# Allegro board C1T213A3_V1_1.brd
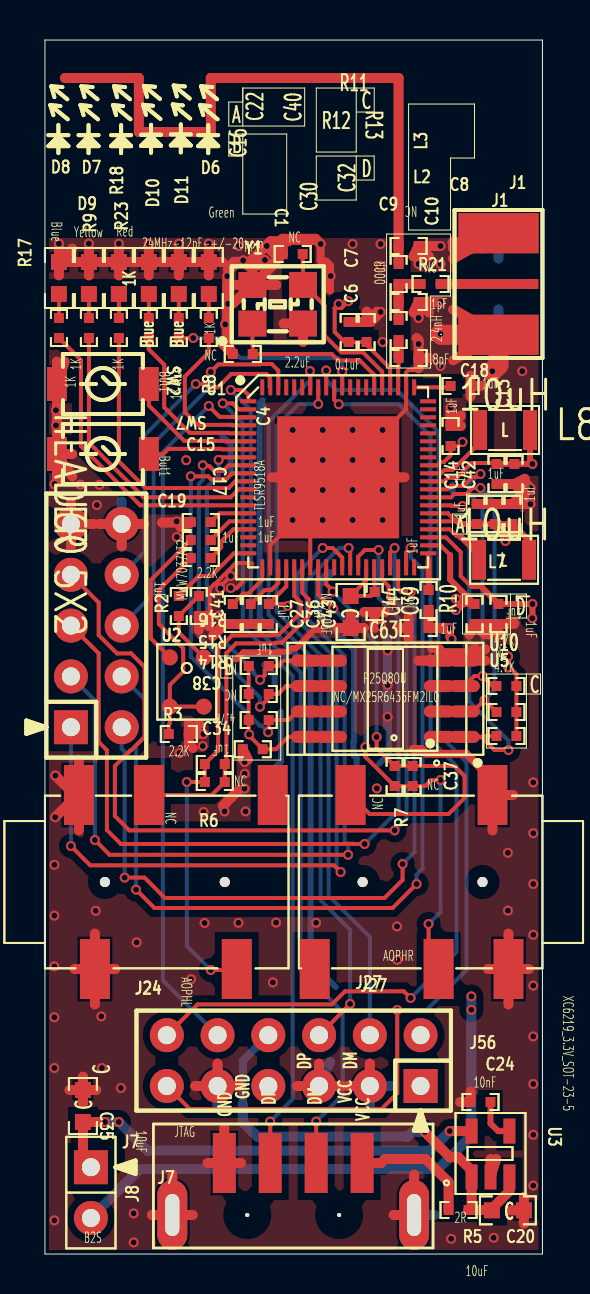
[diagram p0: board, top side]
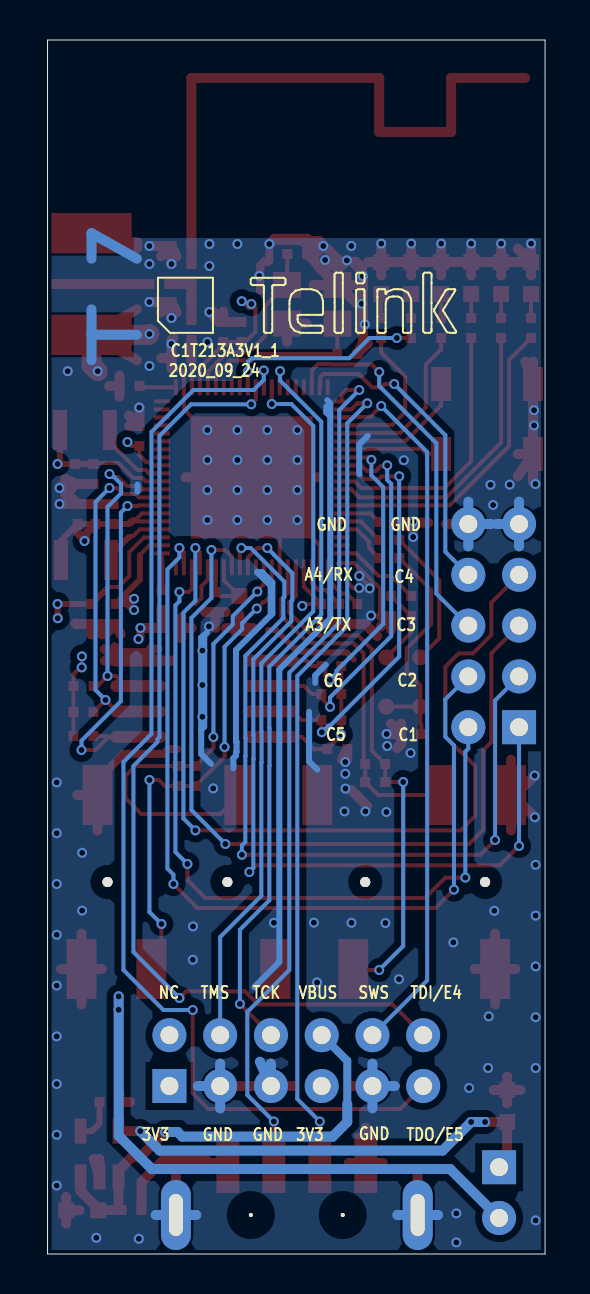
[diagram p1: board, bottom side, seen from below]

Outline 24.9 x 60.7 mm; copper layers: TOP, GND, POWER, BOTTOM. Coordinates in mm from the lower left corner of the outline.
Outline path: 0,60.7 0,0 24.9,0 24.9,60.7 0,60.7

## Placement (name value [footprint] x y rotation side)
C1  NC  [0402]  12.4 50 0 top
C4  NC  [0402]  9.9 45 0 top
C6  2.2uF  [0402]  15.2 46.1 90 top
C7  0.1uF  [0402]  16.1 46.1 90 top
C8  1.8pF  [0402]  18.2 44.8 180 top
C9  1pF  [0402]  18.2 47.6 180 top
C10  1pF  [0402]  18.2 50.4 180 top
C13  1uF  [0402]  20.3 40.9 90 top
C14  1uF  [0402]  22.6 39 270 top
C15  1uF  [0402]  7.8 36.6 0 top
C16  1uF  [0402]  22.5 37 90 top
C17  1uF  [0402]  7.8 35.7 0 top
C18  1uF  [0402]  20.8 43.4 0 top
C19  1uF  [0402]  7.8 34.8 0 top
C20  10uF  [0603C]  23.17 2.18 0 top
C22  1uF  [0402]  21.6 37 90 top
C24  10nF  [0402]  21.8 7.6 180 top
C27  1uF  [0402]  9.4 32 270 top
C30  1uF  [0402]  21.5 32 270 top
C32  1uF  [0402]  22.7 32 270 top
C34  NC  [0402]  8.5 24.5 0 top
C35  10uF  [0603C]  1.9 7.4 90 top
C36  1uF  [0402]  10.3 32 270 top
C37  NC  [0402]  18.4 23.9 90 top
C38  1uF  [0402]  10.4 25.24 180 top
C39  1uF  [0402]  16.5 32.6 270 top
C40  1uF  [0402]  23.4 37 90 top
C41  1uF  [0402]  7.7 32.4 270 top
C42  1uF  [0402]  23.5 39 270 top
C43  1uF  [0402]  11.2 32 270 top
C44  NC/10uF  [0603C]  15.3 32.1 270 top
C63  1uF  [0402]  18.7 31.3 180 top
D6  Green  [0603-LED]  8.2 48.8 90 top
D7  Yellow  [0603-LED]  2.2 48.8 90 top
D8  Blue  [0603-LED]  0.7 48.8 90 top
D9  Red  [0603-LED]  3.7 48.8 90 top
D10  White  [0603-LED]  5.2 48.8 90 top
D11  Orange  [0603-LED]  6.7 48.8 90 top
J1  RFIN  [SMA-H]  22.7 48.5 180 top
J7  USB_SMT_4PIN  [USB-M-4]  12.43 4.55 90 top
J8  B2S  [HDR254F-1X2X850]  2.3 1.8 90 top
J24  AOPHL  [PJ-327]  0 18.6 90 top
J27  AOPHR  [PJ-327]  24.9 18.6 270 top
J56  JTAG  [HDR254F-2X6X850]  6.1 8.4 0 top
J60  HEADER 5X2  [HDR254F-2X5X850]  1.3 36.5 270 top
L2  2.4nH  [0402]  17.7 46.2 90 top
L3  3.3nH  [0402]  17.7 49 90 top
L7  10uH  [1008L]  22.98 34.71 0 top
L8  10uH  [1008L]  23.03 41.2 0 top
R2  2.2K  [0402]  6.7 32.4 270 top
R3  2.2K  [0402]  6.7 26 180 top
R5  2R  [0402]  20.7 2.2 0 top
R6  NC  [0402]  8.5 23.6 0 top
R7  NC  [0402]  17.5 23.9 90 top
R8  1K  [0402]  8.2 46.3 90 top
R9  1K  [0402]  2.2 46.3 90 top
R10  NC  [0402]  19.2 32.7 90 top
R11  4.7K  [0402]  23.1 28.4 180 top
R12  NC  [0402]  23.1 27.1 180 top
R13  4.7K  [0402]  23.1 25.9 180 top
R14  4.7K  [0402]  10.7 26.7 0 top
R15  NC  [0402]  10.7 28 0 top
R16  NC  [0402]  10.7 29.4 0 top
R17  1K  [0402]  0.7 46.3 90 top
R18  1K  [0402]  5.2 46.3 90 top
R19  1K  [0402]  6.7 46.3 90 top
R21  NC  [0402]  19.3 48.5 180 top
R23  1K  [0402]  3.7 46.3 90 top
SW2  But1  [BUTSMD2PX4_00Y3_00_NH]  2.9 43.5 270 top
SW7  But1  [BUTSMD2PX4_00Y3_00_NH]  2.9 40 270 top
U1  TLSR9518A  [QFN_9X9_80PIN_0P4_6P10X6P10]  14.68 38.83 0 top
U2  MWW7037AT2  [GA_BFA423_A83]  7.1 28.6 0 top
U3  LP2985AIM5X-3.8_SOT-23-5  [SOT-23-5]  22.3 5 0 top
U5  P25Q8OU  [W25X10_20_40BL]  17.04 27.76 90 top
U10  NC/MX25R6435FM2IL0  [SOP8_208MIL]  17.04 27.76 90 top
Y1  24MHz-12pF-+/-20ppm  [OSCCC250X320X110]  11.65 47.49 90 top

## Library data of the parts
C1 C4 = C1005_NC
C6 C7 C13-C16 C18 C22 C27 C30 C32 C36 C38-C44 C63 = C1005X5R1C104K
C8-C10 = C1608_NC
C17 C19 C34 C37 = C1005X5R1C105K
C20 C24 C35 = C1608X5R0J106M
D6-D11 = 0603D_Red
J1 = SMA_JACK_2
J7 = USB_SMT_1
J8 = B2S_0: User Part Number: pn; Tolerance: RichardLC
J24 J27 = PJ327_2
J56 = HEADER 6X2: User Part Number: pn; Tolerance: RichardLC
J60 = HEADER 5X2: User Part Number: pn; Tolerance: RichardLC
L2 L3 = MLK1608_000R
L7 L8 = IND: User Part Number: pn; Tolerance: RichardLC
R2 R3 R6 R7 R11-R16 = RS0402K104JT
R5 = RS0402K100JT
R8-R10 R17-R19 R21 R23 = RS0402K332JT
SW2 SW7 = SW2PIN_3x4
U1 = TLSR9518A: User Part Number: pn; Tolerance: RichardLC
U2 = MULPS4CX-RM5_0
U3 = XC6219_1.3V_SOT-23-5
U5 U10 = GD25LD40C_0: Tolerance: RichardLC
Y1 = CRYSTAL4/SM_0: Tolerance: RichardLC

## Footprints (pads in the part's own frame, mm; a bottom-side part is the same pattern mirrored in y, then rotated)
0402
  rect 0.5x0.5 smd: 1(-0.5,0) 2(0.5,0)
0603-LED
  rect 0.8x0.8 smd: A(-0.8,0) C(0.8,0)
0603C
  rect 0.8x0.8 smd: 1(-0.8,0) 2(0.8,0)
1008L
  rect 0.7x2 smd: 1(-1.25,0) 2(1.25,0)
BUTSMD2PX4_00Y3_00_NH
  rect 1.7x1 smd: 1(0,2.3) 2(0,-2.3)
GA_BFA423_A83
  round 0.8 smd: 1(-0.85,1.23) 2(-0.85,-1.23) 3(0.85,-1.23) 4(0.85,1.23)
HDR254F-1X2X850
  rect 1.7x1.7 hole 0.9: 1(2.54,0)
  round 1.7 hole 0.9: 2(0,0)
HDR254F-2X5X850
  rect 1.7x1.7 hole 0.9: 1(10.16,0)
  round 1.7 hole 0.9: 2(10.16,2.54) 3(7.62,0) 4(7.62,2.54) 5(5.08,0) 6(5.08,2.54) 7(2.54,0) 8(2.54,2.54) 9(0,0) 10(0,2.54)
HDR254F-2X6X850
  rect 1.7x1.7 hole 0.9: 1(12.7,0)
  round 1.7 hole 0.9: 2(12.7,2.54) 3(10.16,0) 4(10.16,2.54) 5(7.62,0) 6(7.62,2.54) 7(5.08,0) 8(5.08,2.54) 9(2.54,0) 10(2.54,2.54) 11(0,0) 12(0,2.54)
OSCCC250X320X110
  rect 1.3x1.4 smd: 1(-0.965,1.265) 2(-0.965,-1.265) 3(0.965,-1.265) 4(0.965,1.265)
PJ-327
  round 0.5 hole 1: (0,-3) (0,-9)
  rect 3x1.5 smd: 1(-4.35,-2.5) 2(4.35,-5.2) 3(-4.35,-9.6) 4(4.35,-11.4) 5(4.35,-1.7)
QFN_9X9_80PIN_0P4_6P10X6P10
  rect 0.8x0.2 smd: 1(-4.5,3.8) 2(-4.5,3.4) 3(-4.5,3) 4(-4.5,2.6) 5(-4.5,2.2) 6(-4.5,1.8) 7(-4.5,1.4) 8(-4.5,1) 9(-4.5,0.6) 10(-4.5,0.2) 11(-4.5,-0.2) 12(-4.5,-0.6) 13(-4.5,-1) 14(-4.5,-1.4) 15(-4.5,-1.8) 16(-4.5,-2.2) 17(-4.5,-2.6) 18(-4.5,-3) 19(-4.5,-3.4) 20(-4.5,-3.8) 41(4.5,-3.8) 42(4.5,-3.4) 43(4.5,-3) 44(4.5,-2.6) 45(4.5,-2.2) 46(4.5,-1.8) 47(4.5,-1.4) 48(4.5,-1) 49(4.5,-0.6) 50(4.5,-0.2) 51(4.5,0.2) 52(4.5,0.6) 53(4.5,1) 54(4.5,1.4) 55(4.5,1.8) 56(4.5,2.2) 57(4.5,2.6) 58(4.5,3) 59(4.5,3.4) 60(4.5,3.8)
  rect 0.2x0.8 smd: 21(-3.8,-4.5) 22(-3.4,-4.5) 23(-3,-4.5) 24(-2.6,-4.5) 25(-2.2,-4.5) 26(-1.8,-4.5) 27(-1.4,-4.5) 28(-1,-4.5) 29(-0.6,-4.5) 30(-0.2,-4.5) 31(0.2,-4.5) 32(0.6,-4.5) 33(1,-4.5) 34(1.4,-4.5) 35(1.8,-4.5) 36(2.2,-4.5) 37(2.6,-4.5) 38(3,-4.5) 39(3.4,-4.5) 40(3.8,-4.5) 61(3.8,4.5) 62(3.4,4.5) 63(3,4.5) 64(2.6,4.5) 65(2.2,4.5) 66(1.8,4.5) 67(1.4,4.5) 68(1,4.5) 69(0.6,4.5) 70(0.2,4.5) 71(-0.2,4.5) 72(-0.6,4.5) 73(-1,4.5) 74(-1.4,4.5) 75(-1.8,4.5) 76(-2.2,4.5) 77(-2.6,4.5) 78(-3,4.5) 79(-3.4,4.5) 80(-3.8,4.5)
  rect 6.1x6.1 smd: 81(0,0)
SMA-H
  rect 4x0.5 smd: 1(0,0)
  rect 4x2 smd: 2(0,-2.54) 3(0,2.54) 4(0,-2.54) 5(0,2.54)
SOP8_208MIL
  oval 0.6x1.55 smd: 1(-1.905,-3.95) 2(-0.635,-3.95) 3(0.635,-3.95) 4(1.905,-3.95) 5(1.905,3.95) 6(0.635,3.95) 7(-0.635,3.95) 8(-1.905,3.95)
SOT-23-5
  rect 0.6x1.25 smd: 1(-0.95,-1.145) 2(0,-1.145) 3(0.95,-1.145) 4(0.95,1.145) 5(-0.95,1.145)
USB-M-4
  round 0.2 hole 1.7 unplated: (-2.6,2.3) (-2.6,-2.3)
  rect 3x1.15 smd: 1(0,-3.45) 2(0,-1.15) 3(0,1.15) 4(0,3.45)
  oval 3.5x1.5 hole 2.1x0.7: S1(-2.6,6.05) S2(-2.6,-6.05)
W25X10_20_40BL
  oval 0.6x1.55 smd: 1(-1.905,-2.7) 2(-0.635,-2.7) 3(0.635,-2.7) 4(1.905,-2.7) 5(1.905,2.7) 6(0.635,2.7) 7(-0.635,2.7) 8(-1.905,2.7)

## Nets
GND: C1.1 C4.1 C6.2 C7.2 C8.1 C9.1 C10.1 C13.2 C14.2 C15.1 C16.2 C18.2 C20.2 C22.2 C24.2 C27.2 C30.2 C32.2 C35.2 C36.2 C38.2 C39.2 C40.2 C41.2 C42.2 C43.2 C44.2 C63.2 D6.C(CATHODE) D7.C(CATHODE) D8.C(CATHODE) D9.C(CATHODE) D10.C(CATHODE) D11.C(CATHODE) J1.2 J1.3 J1.4 J1.5 J7.4(GND) J7.S1 J7.S2 J24.1 J24.5 J27.1 J27.5 J56.3 J56.5 J56.9 J60.9 J60.10 R3.1 SW2.2 SW7.2 U1.22(VSSA) U1.27(VSSAO) U1.36(DVSS) U1.62(GANT) U1.81(GND) U3.2(VSS) U5.4(VSS) U10.4(VSS) Y1.2 Y1.4
TL_AINL1: C19.1 R3.2 U2.2(GND#2) U2.3(GND#3)
TL_AIPL1: C17.1 U2.1(OUTPUT)
TL_ANT: C8.2 L2.1 U1.63(ANT)
TL_AONHPL: C34.2 J24.2 R6.2 U1.26(AONHPL)
TL_AONHPR: C37.1 J27.2 R7.1 U1.28(AONHPR)
TL_AOPHPL: C34.1 J24.3 R6.1 U1.25(AOPHPL)
TL_AOPHPR: C37.2 J27.3 R7.2 U1.29(AOPHPR)
TL_AVD: C14.1 C38.1 C42.1 C43.1 L8.2 R11.1 R12.1 R13.1 R14.1 R15.1 R16.1 U1.24(AVD) U1.50(FVDD1V8) U5.8(VCC) U10.8(VCC)
TL_AVDD1V4: C6.1 C7.1 C16.1 C22.1 C40.1 L7.2 U1.45(DVDD1V4) U1.46(AVDD1V4) U1.64(VLINE_PAD)
TL_MICBIAS: R2.1 U1.20(MICBIAS1)
TL_PA3_UART0_TX: J60.6 U1.78(PA[3])
TL_PA4_UART0_RTX: J60.8 U1.79(PA[4])
TL_PA5_DM: J7.2(D-) U1.1(PA[5])
TL_PA6_DP: J7.3(D+) U1.2(PA[6])
TL_PA7_SWS: J56.10 U1.3(PA[7])
TL_PB0_P5: R8.1 U1.4(PB[0])
TL_PB1_P3: R18.1 U1.5(PB[1])
TL_PB2: SW2.1 U1.6(PB[2])
TL_PB3: SW7.1 U1.7(PB[3])
TL_PB4_P0: R23.1 U1.11(PB[4])
TL_PB5_P1: R9.1 U1.12(PB[5])
TL_PB7_P2: R17.1 U1.14(PB[7])
TL_PC1: J60.1 U1.31(PC[1])
TL_PC2: J60.3 U1.32(PC[2])
TL_PC3: J60.5 U1.33(PC[3])
TL_PC4: J60.7 U1.37(PC[4])
TL_PC5: J60.2 U1.38(PC[5])
TL_PC6: J60.4 U1.39(PC[6])
TL_PE3_P0: R19.1 U1.70(PE[3])
TL_PE4_TDI: J56.12 U1.71(PE[4])
TL_PE5_TDO: J56.11 U1.72(PE[5])
TL_PE6_TMS: J56.4 U1.73(PE[6])
TL_PE7_TCK: J56.6 U1.74(PE[7])
TL_PF0_MOSI: R16.2 U1.8(PF[0]) U5.5(SI/IO0) U10.5(SI/IO0)
TL_PF1_MCLK: R15.2 U1.9(PF[1]) U5.6(SCLK) U10.6(SCLK)
TL_PF2_MSIO3: R14.2 U1.10(PF[2]) U5.7(HOLD/IO3) U10.7(HOLD/IO3)
TL_PF3_MSCN: R13.2 U1.47(PF[3]) U5.1(C\S\) U10.1(C\S\)
TL_PF4_MISO: R12.2 U1.48(PF[4]) U5.2(SO/IO1) U10.2(SO/IO1)
TL_PF5_MSIO2: R11.2 U1.49(PF[5]) U5.3(W\P\/IO2) U10.3(W\P\/IO2)
TL_RST: C18.1 U1.61(RESETB)
TL_VBAT: C30.1 J8.2 U1.42(VBAT)
TL_VBUS: C20.1 C63.1 J56.8 R5.2 R10.1 U3.1(VIN) U3.3(CE)
TL_VDD3_DCDC: C13.1 C32.1 J56.1 J56.7 U1.43(VDD3_DCDC) U1.52(AVDD3)
TL_VDDDEC: C39.1 C44.1 U1.34(VDDCORE) U1.35(VDDDEC)
TL_XC1: C1.2 U1.65(XC1) Y1.3
TL_XC2: C4.2 U1.66(XC2) Y1.1
N19932090: C9.2 L2.2 L3.1 R21.2
N19932678: D6.A(ANODE) R8.2
N19932682: D7.A(ANODE) R9.2
N19932684: D8.A(ANODE) R17.2
N19932722: D9.A(ANODE) R23.2
N19933805: C24.1 U3.4(NC)
N19933807: C35.1 J8.1 U3.5(VOUT)
N19933809: J7.1(5V) R5.1
N19934408: C41.1 R2.2 U2.4(VDD)
N19952247: C17.2 U1.16(AIPL1)
N19952336: C19.2 U1.17(AINL1)
N19954124: L8.1 U1.51(VDD1V8_O)
N19954165: L7.1 U1.44(VDD1V4_O)
N19959102: C36.1 U1.23(VREFP_CODEC)
N19959110: C27.1 U1.21(VCAP)
N19961012: C15.2 U1.15(VDD25EF)
N19962035: R10.2 U1.41(VBUS)
N19963346: J1.1 R21.1
N19965304: C10.2 L3.2
N19973716: D10.A(ANODE) R18.2
N19973830: D11.A(ANODE) R19.2

Pads without a net: J24 4; J27 4; J56 2; U1 13 18 19 30 40 53 54 55 56 57 58 59 60 67 68 69 75 76 77 80

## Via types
v1: diameter 0.5, hole 0.3, TOP to BOTTOM, 185 vias

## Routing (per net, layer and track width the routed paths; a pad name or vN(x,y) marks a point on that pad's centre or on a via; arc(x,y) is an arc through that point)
GND: length 318.7
  TOP w0.2: 8.49,33.48 8.88,33.48 v1(9.3,33.9) ; 8.49,33.48 8.46,33.48 8.25,33.27 8.25,32.1 ; 8.49,33.48 9.56,34.55 10.33,34.55 10.37,34.51 ; v1(9.3,33.3) 9.31,33.29 9.59,33.29 9.88,33.58 ; 17.5,32.5 17.2,32.8 17.2,33.39 16.88,33.71 U1.36 ; U5.4 U10.4 ; U1.27 13.28,37.43 ; 13.28,37.43 11.28,35.43 U1.22 ; 13.28,37.43 U1.81 18.08,42.23 U1.62 18.08,44.08 18.2,44.2 18.62,44.2 18.7,44.28 ; v1(9.92,49.68) 9.46,49.22 9.45,49.22 v1(9.12,48.89)
  TOP w0.3: 13.87,31.2 13.48,31.2 12.56,30.29 12.36,30.29 12.19,30.12 11.75,30.12 11.71,30.08 9.93,30.08 9.57,29.72
  TOP w0.4: 18.41,25.25 18.85,25.25 19.09,25.01 21.09,25.01 22.4,23.7 J27.1 ; 14.27,48.18 14.26,48.19 14.26,49.42 14.06,49.62 13.85,49.62 13.8,49.67 v1(13.8,50.5) ; 10.65,49.66 10.65,49.95 v1(11.1,50.4) ; 10.65,49.66 9.44,49.66 9.12,49.34 v1(9.12,48.89) ; 10.65,49.66 10.97,49.66 v1(11.01,49.7) ; 19.34,30.26 19.58,30.26 19.75,30.09 21.25,30.09 21.55,30.39 ; 13.65,50.65 12.25,50.65 12.19,50.59 12.16,50.59
  TOP w0.5: 9.12,46.58 9.12,45.76 8.88,45.52 C4.1 9.14,45.52 ; 9.12,46.58 9.12,48.35 ; 9.12,46.58 v1(9.02,46.48) ; C44.2 15.97,31.3 ; C44.2 15.3,31.97 ; C44.2 14.63,31.3 ; C42.2 24.1,38.5 v1(24.3,38.3) ; C42.2 24.02,38.76 ; C42.2 C14.2 ; C42.2 24.02,37.98 ; 22.24,50.58 21.95,50.29 20.41,50.29 ; 22.24,50.58 20.39,50.58 ; 22.24,50.58 J1.2 ; D8.C 1.37,50.27 ; D8.C v1(0.7,50.52) ; D8.C 0.7,48.93 ; D8.C D7.C ; 10.11,49.49 10.16,49.44 ; 10.11,49.49 10.14,49.49 11.29,50.64 11.77,50.64 11.89,50.76 13.54,50.76 v1(13.8,50.5) ; 10.11,49.49 v1(9.92,49.68) ; 10.16,49.44 10.39,49.21 Y1.4 ; 10.16,49.44 11.34,49.44 C1.1 ; 17.45,1.95 18.48,1.95 18.48,3.97 ; J24.1 2.5,16.02 ; J24.1 2.5,12.48 ; J24.1 1.48,14.25 ; J24.1 3.52,14.25 ; J7.S1 6.38,3.97 ; J7.S1 5.35,1.95 ; J7.S1 7.4,1.95 ; 22.18,30.98 C32.2 ; C32.2 C30.2 ; C32.2 22.7,30.98 22.39,31.29 21.5,31.29 C30.2 ; C32.2 23.47,31.5 23.5,31.53 ; 3.7,48.93 D9.C ; D9.C 3.03,49.6 ; D9.C 3.7,50.27 ; D9.C 4.37,49.6 ; 17.68,31.3 C63.2 ; C63.2 18.2,31.82 ; C63.2 18.2,30.78 ; 9.7,23.2 8.9,22.4 ; v1(0.48,38.5) 0.6,38.62 SW7.2 ; v1(0.52,23.92) 1.49,22.95 1.62,22.95 ; 9.12,48.35 9.22,48.45 Y1.4 ; 9.12,48.35 v1(9.12,48.89) ; 5.85,36.57 7.27,36.57 C15.1 ; 1.23,8.2 C35.2 ; C35.2 1.9,7.53 ; C35.2 2.57,8.2 ; C35.2 1.9,8.87 ; 20.43,47.23 J1.3 20.43,44.69 ; C39.2 16.5,31.31 ; C39.2 17.02,32.1 ; C39.2 15.98,32.1 ; SW7.2 1.37,38.88 ; SW7.2 1.37,40 ; SW7.2 SW2.2 ; C10.1 v1(18.7,49.5) ; C10.1 v1(19.8,50.4) ; C10.1 19.22,49.88 ; C10.1 18.44,49.88 ; C41.2 8.22,31.38 ; C41.2 8.22,31.9 ; C41.2 7.7,31.2 ; 8.98,4.55 8.98,6.32 ; 8.98,4.55 9.82,4.55 ; 8.98,4.55 8.13,4.55 ; v1(16.8,47.1) 16.3,46.6 C7.2 ; C13.2 20.82,41.92 ; C13.2 20.3,42.31 v1(20.31,42.32) ; C13.2 20.82,41.4 ; 11.36,38.83 U1.81 18,38.83 ; J56.9 8.64,9.52 ; J56.9 7.52,8.4 ; J56.9 9.76,8.4 ; 22.59,4.75 U3.2 22.3,4.75 ; C8.1 19.22,44.8 ; C8.1 v1(18.7,45.5) 18.7,45.7 18.6,45.8 ; C8.1 18.7,44.28 ; 11.57,48.45 11.57,48.45 Y1.4 ; 5.2,48.93 D10.C ; D10.C 5.2,50.27 ; D10.C 5.87,49.6 ; D10.C 4.53,49.6 ; 20.43,50.4 J1.2 ; J1.2 20.43,49.77 ; Y1.4 11.36,49.37 ; Y1.4 9.42,47.53 ; 22.18,14.25 J27.5 ; J27.5 23.2,12.48 ; J27.5 23.2,16.02 ; J27.5 24.22,14.25 ; 1.62,22.95 J24.5 ; 1.62,22.95 v1(0.51,21.84) ; J24.5 1.7,21.18 ; J24.5 1.7,24.72 ; 15.14,8.4 J56.3 16.26,9.52 ; 23.42,22.95 J27.1 22.4,21.18 ; D7.C 2.87,49.6 ; D7.C 2.2,50.27 ; D7.C 2.2,48.93 ; 12.6,8.4 J56.5 ; J56.5 13.72,9.52 ; J56.5 14.84,8.4 ; 23.97,1.51 C20.2 ; C20.2 23.3,2.18 ; C20.2 23.97,2.85 ; 22.04,30.24 U10.4 22.04,29.67 ; C9.1 19.22,47.08 ; C9.1 v1(19.8,47.6) ; C9.1 v1(18.7,46.8) ; C9.1 18.44,47.08 ; 21.3,42.88 C18.2 ; C18.2 21.82,43.4 ; C18.2 21.3,43.92 ; D11.C 7.37,49.6 ; D11.C 6.03,49.6 ; D11.C 6.7,48.93 ; D11.C 6.7,50.27 ; R3.1 7.2,26.52 ; R3.1 v1(7.93,26) ; R3.1 7.72,26.52 ; R3.1 7.2,25.5 7.4,25.3 ; C30.2 22.02,30.98 ; C30.2 21.24,30.98 ; 18.69,29.67 U5.4 19.74,30.24 ; 11.95,46.52 Y1.2 12.92,45.6 ; 11.38,50.52 C1.1 ; C1.1 11.5,50 v1(11.1,50.4) ; C1.1 11.9,50.52 ; 7.53,49.6 D6.C ; D6.C 8.2,50.27 ; D6.C 8.2,48.93 ; D6.C 8.87,49.6 ; 21.3,8.12 C24.2 20.78,7.6 ; C15.1 6.78,36.34 ; C15.1 6.78,36.6 ; 3.84,35.38 J60.10 ; J60.10 4.96,36.5 ; J60.10 2.72,36.5 ; 10.16,24.72 C38.2 9.9,24.72 ; C22.2 C16.2 C40.2 ; C40.2 23.92,38.02 ; C40.2 v1(24.3,37.5) ; C40.2 23.92,37.76 ; SW2.2 0.99,44.62 ; SW2.2 0.6,44.62 ; J60.9 2.42,36.5 ; J60.9 1.3,37.62 ; J60.9 1.3,35.38 ; C7.2 16.1,47.12 ; C7.2 16.62,47.12 ; C7.2 C6.2 ; 8.4,30.9 9,31.5 C27.2 C36.2 C43.2
  TOP w1: v1(22.39,44.14) 22.7,44.45 J1.3 19.84,45.96 v1(19.8,46)
  BOTTOM w0.2: 11.76,26.87 11.76,26.01
  BOTTOM w0.3: 13.73,31.94 15.47,30.2 15.47,25.63 15.44,25.6 15.44,25.1 15.47,25.07 15.47,24.92 15.6,24.79 15.6,24.29 ; 13.73,31.94 13.65,32.02 13.65,33.58 14.16,34.09 14.41,34.09 13.73,33.41 13.73,31.94 ; 8.87,40.91 9.3,40.48 9.3,38.99 ; 11.4,24.22 11.81,24.63 11.81,27.11 ; 10.9,42.69 10.75,42.54 10.75,41.88 ; 11.5,28.56 11.5,28.93 10.97,29.46 ; 16.93,31.06 17.06,30.93 17.06,26.37 17.21,26.22 ; 20.4,38.47 20.4,38.12 ; 14.55,13.35 13.3,14.6 13.3,29.23 10.75,31.78 10.75,41.88 ; 16.72,24.51 17.21,25 17.21,26.22 ; 17.21,26.22 17.21,30.82 17.09,30.94 ; 10.75,41.88 10.95,42.08 10.95,42.38
  BOTTOM w0.5: 20.43,49.77 J1.2 22.7,49.77 ; 20.43,45.96 J1.3 ; J1.3 22.7,47.23 ; J1.3 22.7,44.69 ; 7.52,8.4 J56.9 ; J56.9 8.64,7.28 ; J56.9 8.64,9.52 ; 16.26,7.28 J56.3 ; J56.3 17.38,8.4 ; J56.3 16.26,9.52 ; J60.9 2.42,36.5 ; J60.9 1.3,37.62 ; J60.9 1.3,35.38 ; 13.72,9.52 J56.5 14.27,9.61 ; 19.5,1.95 17.45,1.95 ; J60.10 3.84,37.62 ; J60.10 2.72,36.5 ; J60.10 3.84,35.38 ; 5.35,1.95 J7.S1 7.4,1.95
  vias: v1(0.47,19.46) v1(0.47,16.92) v1(0.47,14.38) v1(0.47,11.84) v1(0.47,9.3) v1(0.47,1.68) v1(0.55,42.19) v1(0.55,41.43) v1(1.77,38.47) v1(2.2,50.52) v1(2.54,17.16) v1(2.6,37.45) v1(2.73,38.46) v1(2.82,11.88) v1(2.85,9.3) v1(3.7,50.52) v1(3.8,8.3) v1(4.44,2.03) v1(4.44,0.58) v1(4.59,15.58) v1(5.2,50.52) v1(6.59,36.63) v1(6.6,35.85) v1(6.7,50.52) v1(6.73,25.05) v1(7.07,39.69) v1(7.31,13.74) v1(7.9,25.4) v1(7.94,22.1) v1(7.99,16.55) v1(8.2,50.52) v1(8.71,31.92) v1(8.78,33.28) v1(8.99,22.13) v1(9.17,47.51) v1(9.7,50.4) v1(9.69,16.56) v1(10,24.6) v1(10,24.01) v1(9.99,23.27) v1(10.04,22.13) v1(11.41,13.58) v1(11.57,16.57) v1(12.4,41.2) v1(12.4,39.7) v1(12.4,38.2) v1(12.4,36.7) v1(13.57,16.56) v1(13.9,41.2) v1(13.9,39.7) v1(13.9,38.2) v1(13.9,36.7) v1(14.3,48.9) v1(15.4,50.5) v1(15.4,41.2) v1(15.4,39.7) v1(15.4,38.2) v1(15.4,36.7) v1(16.61,23.28) v1(16.8,50.5) v1(16.8,49.4) v1(16.82,31.38) v1(16.9,45.6) v1(16.9,41.2) v1(16.9,39.7) v1(16.9,38.2) v1(16.9,36.7) v1(17.15,30.17) v1(17.15,28.45) v1(17.15,26.86) v1(17.62,16.38) v1(17.63,14.71) v1(19.8,49.5) v1(19.8,44.4) v1(20.33,0.76) v1(22.46,0.81) v1(23.17,20.06) v1(23.17,17.17) v1(23.89,44.14) v1(24.44,23.58) v1(24.44,21.04) v1(24.44,18.5) v1(24.44,15.96) v1(24.44,13.42) v1(24.44,10.88) v1(24.44,8.5) v1(24.44,5.96) v1(24.44,3.42)
TL_AINL1: length 12
  TOP w0.2: U2.2 6.25,26.52 6.2,26.47 R3.2 ; U2.2 U2.3 ; U2.2 6.25,28.45 6.92,29.12 6.92,30.28 5.7,31.5 5.7,33.2 C19.1
TL_AIPL1: length 7.1
  TOP w0.2: U2.1 5.3,30.78 5.3,33.7 C17.1
TL_ANT: length 2.4
  TOP w0.2: C8.2 17.7,44.33 17.68,44.31 U1.63
  TOP w0.5: C8.2 L2.1
TL_AONHPL: length 18
  TOP w0.2: J24.2 8.35,22.95 R6.2 C34.2 9.08,24.58 9.08,30.04 9.57,30.53 11.53,30.53 11.56,30.57 11.86,30.57 13.2,31.9 13.2,32.74 12.88,33.07 U1.26
TL_AONHPR: length 24.9
  TOP w0.2: v1(16.04,25.35) 16.04,24.86 R7.1 C37.1 19.03,23.4 19.33,23.7 v1(19.8,23.7) ; v1(19.2,16.5) 19.2,14.75 J27.2 ; U1.28 13.68,32.96 14.04,32.6 14.1,32.6 v1(14.43,32.27)
  BOTTOM w0.2: v1(14.43,32.27) 15.16,31.54 15.16,31.24 16.04,30.36 v1(16.04,25.35) ; v1(19.8,23.7) 19.8,17.1 v1(19.2,16.5)
TL_AOPHPL: length 26.3
  TOP w0.2: v1(7.1,23.6) R6.1 C34.1 8.67,25.17 8.67,30.24 9.36,30.93 11.36,30.93 11.4,30.97 11.7,30.97 12.8,32.07 12.8,32.58 12.48,32.9 U1.25 ; v1(8.3,14.2) 9.55,14.2 J24.3
  BOTTOM w0.2: v1(7.1,23.6) 7.1,15.4 v1(8.3,14.2)
TL_AOPHPR: length 22.6
  TOP w0.2: v1(16.6,25.85) 16.6,25.3 R7.2 C37.2 20.5,24.4 21,23.9 21,22.8 20.2,22 16.25,22 J27.3 ; v1(14.4,33.12) 14.4,33.17 14.08,33.49 U1.29
  BOTTOM w0.2: v1(14.4,33.12) 15.63,31.89 15.63,31.47 16.6,30.5 v1(16.6,25.85)
TL_AVD: length 22.9
  TOP w0.2: v1(23.18,29.88) 23.19,29.87 v1(23.19,29.33) 23.27,29.33 23.6,29 R11.1 R12.1 R13.1 ; U5.8 U10.8 12.18,25.86 11.56,25.24 C38.1 10.2,25.94 10.2,26 ; 10.2,26 R14.1 R15.1 R16.1 ; 10.2,26 v1(10.22,25.98) ; U1.24 12.08,33.38 C43.1 12,32.5 12.1,32.4 v1(12.15,32.4) ; C14.1 22.55,39.55 21.35,39.55 20.6,38.8 20.16,38.8 19.99,38.63 U1.50
  TOP w0.3: C14.1 C42.1 v1(24.4,39.5) 24.28,39.62 L8.2
TL_AVDD1V4: length 17.7
  TOP w0.2: 15.04,47.5 v1(14.7,47.5) 14.5,47.3 ; 15.04,47.5 14.84,47.3 14.5,47.3 ; 15.04,47.5 v1(15.18,47.64) ; 20.57,36.63 20.17,37.03 U1.46 ; 20.57,36.63 20.7,36.5 20.86,36.5 ; 20.57,36.63 U1.45 ; 14.5,47.3 14.5,46.1 15,45.6 C6.1 C7.1 16.1,45.46 17.28,44.29 U1.64
  TOP w0.3: L7.2 24.23,35.67 C40.1 C16.1 C22.1 20.86,36.5 20.75,36.61 20.7,36.61 20.61,36.7
  TOP w0.4: 22.67,36.33 C16.1 ; 22.67,36.33 22.67,36.3 22.73,36.24 ; 22.67,36.33 22.97,36.03 22.97,35.73 v1(23.05,35.65) 23.05,35.7 23.4,36.05 C40.1
TL_MICBIAS: length 4.4
  TOP w0.2: R2.1 7.7,33.9 8.32,33.9 9.46,35.03 U1.20
TL_PA3_UART0_TX: length 19
  TOP w0.2: U1.78 11.68,44.18 11.35,44.5 10.78,44.5 10.76,44.48 8.68,44.48 v1(8.3,44.1)
  BOTTOM w0.2: v1(8.3,44.1) 8.3,43.4 5.44,40.54 5.44,33.02 J60.6
TL_PA4_UART0_RTX: length 15.7
  TOP w0.2: v1(7.55,43.5) 8.02,43.5 8.19,43.33 8.66,43.33 9.33,44 11.09,44 11.25,43.85 11.25,43.36 U1.79
  BOTTOM w0.2: v1(7.55,43.5) 4.99,40.94 4.99,35.11 4.6,34.72 J60.8
TL_PA5_DM: length 42.8
  TOP w0.2: v1(13.57,6.62) J7.2 ; U1.1 10.18,42.95 9.93,43.2 v1(9.3,43.2)
  BOTTOM w0.2: v1(13.57,6.62) 14.2,7.25 14.2,7.25 14.9,7.95 14.9,12.1 12.8,14.2 12.8,29.07 10.3,31.57 10.3,42.2 v1(9.3,43.2)
TL_PA6_DP: length 41.3
  TOP w0.2: v1(11.27,6.62) J7.3 ; U1.2 9.7,42.23 9.41,42.52 9.39,42.52 9.37,42.53 v1(8.9,42.53)
  BOTTOM w0.2: v1(8.9,42.53) 9.9,41.53 9.9,31.4 12.4,28.9 12.4,7.75 v1(11.27,6.62)
TL_PA7_SWS: length 35.8
  TOP w0.2: v1(8.2,42.4) 8.74,41.86 9.51,41.86 9.53,41.83 U1.3
  BOTTOM w0.2: v1(8.2,42.4) 5.9,40.1 5.9,13.68 J56.10
TL_PB0_P5: length 7.6
  TOP w0.2: R8.1 8.2,45.07 7,43.87 7,42.1 7.64,41.46 9.34,41.46 9.36,41.43 U1.4
TL_PB1_P3: length 8.5
  TOP w0.2: R18.1 5.2,45.23 5.97,44.46 5.97,42.33 7.24,41.06 9.18,41.06 9.2,41.03 U1.5
TL_PB2: length 6.8
  TOP w0.2: SW2.1 5.2,42.43 6.97,40.66 9.01,40.66 9.03,40.63 U1.6
TL_PB3: length 5.1
  TOP w0.2: U1.7 8.87,40.23 8.84,40.26 6.18,40.26 5.92,40 SW7.1
TL_PB4_P0: length 13.3
  TOP w0.2: R23.1 3.7,39.63 5.03,38.3 9.19,38.3 9.53,38.63 U1.11
TL_PB5_P1: length 14.5
  TOP w0.2: U1.12 9.7,38.23 9.29,37.83 4.93,37.83 2.2,40.57 R9.1
TL_PB7_P2: length 15.5
  TOP w0.2: U1.14 4.77,37.43 1.8,40.4 1.8,44.7 R17.1
TL_PC1: length 39.3
  TOP w0.2: v1(13.9,35.3) 14.4,35.3 14.88,34.82 U1.31 ; v1(1.3,20.4) 2.27,19.43 6.28,19.43 14.47,19.43 v1(14.8,19.1)
  BOTTOM w0.2: v1(14.8,19.1) 14.6,19.3 14.6,24.74 14.59,24.75 14.59,25.95 14.6,25.96 14.6,29.73 12.7,31.63 12.7,32.63 12.65,32.68 12.65,34.04 13.57,34.96 13.57,34.97 v1(13.9,35.3) ; v1(1.3,20.4) J60.1
TL_PC2: length 40
  TOP w0.2: v1(15.2,35.3) 15.28,35.22 U1.32 ; v1(2.5,20.7) 3.24,19.96 v1(15.17,19.96)
  BOTTOM w0.2: J60.3 2.5,27.68 v1(2.5,20.7) ; v1(15.2,35.3) 14.73,35.3 13.05,33.62 13.05,32.85 13.1,32.8 13.1,31.8 15,29.9 15,25.8 14.99,25.79 14.99,24.91 15,24.91 15,20.6 15.17,20.43 v1(15.17,19.96)
TL_PC3: length 41.7
  TOP w0.2: U1.33 15.68,34.87 16.01,35.2 v1(16.7,35.2) ; v1(16,20.5) 15.41,20.5 15.4,20.51 14.94,20.51 14.93,20.5 3.8,20.5 3.1,21.2 3.1,25.19 2.69,25.6 2.69,30.03 J60.5
  BOTTOM w0.2: v1(16.7,35.2) 16.7,32.8 17.7,31.8 17.7,22.2 v1(16,20.5)
TL_PC4: length 44.6
  TOP w0.2: v1(17.5,35.3) 17.28,35.08 U1.37 ; v1(17.5,21.18) 4.22,21.18 3.5,21.9 3.5,24.4 4.29,25.19 4.32,25.19 4.99,25.86 4.99,29.36 4.32,30.03 3.6,30.03 2.69,30.94 2.69,32.57 J60.7
  BOTTOM w0.2: v1(17.5,21.18) 18.1,21.78 18.1,32.06 17.5,32.66 v1(17.5,35.3)
TL_PC5: length 38.8
  TOP w0.2: U1.38 17.68,33.25 17.83,33.1 v1(18.3,33.1) ; v1(17.9,19.5) 17.9,18.7 17,17.8 6,17.8 4.98,18.82 v1(3.99,18.82)
  BOTTOM w0.2: J60.2 3.84,25.27 3.99,25.12 v1(3.99,18.82) ; v1(18.3,33.1) 18.3,32.63 18.5,32.43 18.5,20.1 v1(17.9,19.5)
TL_PC6: length 44.5
  TOP w0.2: v1(4.56,18.22) 5.48,17.3 17.4,17.3 v1(18.6,18.5) ; v1(18.3,35.3) 18.08,35.08 U1.39
  BOTTOM w0.2: J60.4 4.99,27.73 4.99,25.86 4.56,25.43 v1(4.56,18.22) ; v1(18.3,35.3) 18.3,34.83 18.9,34.23 18.9,19.27 18.6,18.97 v1(18.6,18.5)
TL_PE3_P0: length 9.9
  TOP w0.2: U1.70 v1(14.88,44.12) ; R19.1 v1(7.42,45.8)
  BOTTOM w0.2: v1(7.42,45.8) 8.79,45.8 9.8,44.79 14.68,44.79 14.88,44.59 v1(14.88,44.12)
TL_PE4_TDI: length 49
  TOP w0.2: U1.71 14.48,42.71 v1(14.71,42.48) ; J56.12 7.64,12.48 14.36,12.48 15.01,13.13 17.97,13.13 v1(18.3,12.8)
  BOTTOM w0.2: v1(18.3,12.8) 20.6,15.1 20.6,24.4 19.4,25.6 19.4,25.73 19.3,25.83 19.3,40.9 17.72,42.48 v1(14.71,42.48)
TL_PE5_TDO: length 56.3
  TOP w0.2: U1.72 v1(14.08,44.18) ; J56.11 7.25,7.25 16.85,7.25 17.63,8.03 v1(17.63,12.2)
  BOTTOM w0.2: v1(14.08,44.18) 14.08,43.71 14.58,43.2 17.6,43.2 19.7,41.1 19.7,26 21.1,24.6 21.1,14.2 19.1,12.2 v1(17.63,12.2)
TL_PE6_TMS: length 35.8
  TOP w0.2: U1.73 v1(13.68,42.5)
  BOTTOM w0.2: v1(13.68,42.5) 12.7,42.5 11.6,41.4 11.6,32.13 14.2,29.53 14.2,26.13 14.19,26.12 14.19,24.58 14.2,24.57 14.2,17.91 16.26,15.85 J56.4
TL_PE7_TCK: length 37.2
  TOP w0.2: v1(13.26,44.15) 13.28,44.13 U1.74 ; v1(15.27,12.51) 14.94,12.17 14.94,12.16 J56.6
  BOTTOM w0.2: v1(15.27,12.51) 15.27,16.21 13.8,17.68 13.8,24.41 13.79,24.42 13.79,26.28 13.8,26.29 13.8,29.37 11.2,31.97 11.2,41.61 13.26,43.68 v1(13.26,44.15)
TL_PF0_MOSI: length 18
  TOP w0.2: U1.8 8.83,39.83 8.71,39.71 v1(8.69,39.71) ; v1(10.77,28.71) 11,28.94 11,29.2 R16.2 11.67,29.4 11.94,29.67 U10.5 U5.5
  BOTTOM w0.2: v1(8.69,39.71) 8.69,38.93 8.1,38.34 8.1,31.5 10.44,29.16 10.44,29.04 v1(10.77,28.71)
TL_PF1_MCLK: length 20.1
  TOP w0.2: U5.6 U10.6 12.07,28.4 11.67,28 R15.2 11.2,27.8 v1(10.76,27.36) ; U1.9 9.2,39.43 8.91,39.15 8.47,39.15 8.22,39.4 7.93,39.4 v1(7.9,39.43)
  BOTTOM w0.2: v1(10.76,27.36) 10.76,27.83 7.7,30.89 7.7,38.51 7.9,38.71 v1(7.9,39.43)
TL_PF2_MSIO3: length 21.4
  TOP w0.2: v1(11.17,26.09) 11.2,26.12 R14.2 12.19,26.7 12.61,27.13 U10.7 U5.7 ; v1(7.3,38.88) 8.17,38.88 8.31,38.75 9.08,38.75 9.36,39.03 U1.10
  BOTTOM w0.2: v1(7.3,38.88) 7.3,29.87 10.75,26.42 10.84,26.42 v1(11.17,26.09)
TL_PF3_MSCN: length 19.4
  TOP w0.2: R13.2 22.03,25.9 21.98,25.86 21.84,25.86 ; U5.1 U10.1 21.84,25.86 ; v1(20.9,37.4) 20.37,37.4 20.33,37.43 U1.47 ; 21.84,25.86 22.5,25.2 v1(23.2,25.2)
  BOTTOM w0.2: v1(23.2,25.2) 23.2,25.67 21.23,27.64 21.23,37.07 v1(20.9,37.4)
TL_PF4_MISO: length 17.3
  TOP w0.2: U5.2 U10.2 21.43,27.13 v1(22,27.7) R12.2 ; v1(21.8,38.3) 21.4,38.3 21.1,38 20.49,38 20.32,37.83 U1.48
  BOTTOM w0.2: v1(21.8,38.3) 22.5,37.6 22.5,28.2 v1(22,27.7)
TL_PF5_MSIO2: length 16.9
  TOP w0.2: R11.2 22.4,28.4 v1(21.9,28.9) 21.49,28.9 U10.3 U5.3 ; v1(21.8,39) 21.65,38.85 21.38,38.85 20.93,38.4 20.32,38.4 20.16,38.23 U1.49
  BOTTOM w0.2: v1(21.9,28.9) 21.9,37.35 21.22,38.03 21.22,38.5 21.57,38.85 21.65,38.85 v1(21.8,39)
TL_RST: length 1.9
  TOP w0.2: U1.61 20.23,43.33 C18.1
TL_VBAT: length 33.8
  TOP w0.2: U1.42 19.8,35.43 20.28,34.95
  TOP w0.3: 21.22,32.5 20.87,32.5 ; 21.22,32.5 20.92,32.8 20.61,32.8 v1(20.57,32.76) ; 21.22,32.5 C30.1 20.28,33.72 20.28,34.95
  TOP w0.4: 20.87,32.5 v1(20.57,32.2)
  BOTTOM w0.5: J8.2 4.75,4.25 19.68,4.25 21.34,5.91 v1(21.34,12.21) v1(21.34,12.88)
TL_VBUS: length 25.3
  TOP w0.4: v1(20.25,31.3) 20.25,30.85 v1(20.35,30.75)
  TOP w0.5: v1(20.25,31.3) C63.1 R10.1 ; U3.3 23.25,3.15 22.37,2.27 C20.1 22.35,2.2 R5.2 21.35,2.35 U3.1 21.35,4.18 20.69,4.84 20.27,4.84 v1(19.01,6.1)
  BOTTOM w0.4: 9.9,7.5 9.9,9.66 J56.8
  BOTTOM w0.5: v1(19.01,6.1) 18.39,6.1 18.16,5.87 10.63,5.87 9.9,6.6 9.9,7.5
TL_VDD3_DCDC: length 10.5
  TOP w0.2: U1.52 19.66,39.43 19.82,39.6 19.97,39.6 20.3,39.93 C13.1 20.7,40.4 v1(20.9,40.6) ; 21.85,33.35 21.35,33.35 20.81,33.89 20.81,35.09 20.07,35.83 U1.43
  TOP w0.3: 21.85,33.35 C32.1 v1(24.4,32.5) 24.4,31.8 v1(24.39,31.79)
TL_VDDDEC: length 4.3
  TOP w0.2: U1.34 16.08,33.68 C44.1 16.3,32.9 C39.1 16.5,33.57 16.48,33.59 U1.35
TL_XC1: length 9
  TOP w0.2: C1.2 12.9,49.34 12.92,49.32 Y1.3 12.97,48.45 14,47.42 14,45.92 14.84,45.08 15.92,45.08 16.88,44.12 U1.65
TL_XC2: length 8.7
  TOP w0.2: U1.66 16.48,43.95 15.75,44.68 14.67,44.68 14.35,45 C4.2 10.4,45.47 10.39,45.48 Y1.1
N19932090: length 2.9
  TOP w0.5: L2.2 C9.2 L3.1 R21.2
N19932678: length 1.2
  TOP w0.2: D6.A R8.2
N19932682: length 1.2
  TOP w0.2: R9.2 D7.A
N19932684: length 1.2
  TOP w0.2: R17.2 D8.A
N19932722: length 1.2
  TOP w0.2: R23.2 D9.A
N19933805: length 2.2
  TOP w0.3: U3.4 22.68,6.14 22.3,6.53 C24.1
N19933807: length 22.9
  TOP w0.5: v1(3,6.6) C35.1 1.9,4.74 J8.1 ; U3.5 v1(20.26,6.14)
  BOTTOM w0.5: v1(3,6.6) v1(3.7,6.6) 5.13,5.17 19.29,5.17 v1(20.26,6.14)
N19933809: length 6.3
  TOP w0.5: J7.1 16.82,4.55 17.02,4.75 19.05,4.75 20.2,3.6 R5.1
N19934408: length 4
  TOP w0.2: U2.4 6.7,31.08 R2.2 C41.1
N19952247: length 2.3
  TOP w0.2: U1.16 9.23,36.63 C17.2
N19952336: length 2.6
  TOP w0.2: U1.17 9.43,36.23 8.82,35.62 8.82,35.34 8.71,35.22 8.71,35.21 C19.2
N19954124: length 3.9
  TOP w0.2: U1.51 19.8,39.03 19.83,39.06 19.85,39.06 19.99,39.2 20.4,39.2 21.78,40.58 L8.1
N19954165: length 3.3
  TOP w0.2: 20.8,35.83 20.73,35.9 20.6,35.9 20.27,36.23 U1.44
  TOP w0.3: 20.8,35.83 20.85,35.83 21.73,34.95 L7.1
N19959102: length 2.6
  TOP w0.2: C36.1 11,33.2 11.33,33.2 11.68,33.54 U1.23
N19959110: length 2.6
  TOP w0.2: C27.1 9.92,33.02 10.18,33.02 10.88,33.71 U1.21
N19961012: length 2.1
  TOP w0.2: C15.2 8.73,37.03 U1.15
N19962035: length 1.8
  TOP w0.2: U1.41 19.18,34.71 19.2,34.69
  TOP w0.3: R10.2 19.2,34.69
N19963346: length 2.9
  TOP w0.5: R21.1 J1.1
N19965304: length 31.4
  TOP w0.5: L3.2 C10.2 17.7,58.8 8.3,58.8 8.3,56.1 4.7,56.1 4.7,58.8 1,58.8
N19973716: length 1.2
  TOP w0.2: D10.A R18.2
N19973830: length 1.2
  TOP w0.2: D11.A R19.2

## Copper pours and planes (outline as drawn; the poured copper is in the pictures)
GND on TOP: 0.2,0.2 0.2,60.5 24.7,60.5 24.7,50.06 20.56,50.06 20.56,46.94 24.7,46.94 24.7,0.2 ; 20 cut-outs
GND on BOTTOM: 0.2,0.2 0.2,60.5 24.7,60.5 24.7,0.2 ; 8 cut-outs
GND on GND: 0.2,0.2 0.2,60.5 24.7,60.5 24.7,0.2 ; 2 cut-outs
TL_AVD on POWER: 7.64,24.38 7.6,33.3 7.6,41.2 17.5,41.2 17.5,35.3 23.4,35.3 23.25,36.59 19.8,36.8 19.8,39.62 20.4,39.62 20.4,39.6 22.7,39.6 22.7,41.2 24.7,41.2 24.7,33.1 23.56,33.1 23.56,27.3 22.3,27.3 22.3,33.3 22.28,33.3 22.28,33.65 19.92,33.65 19.92,33.3 12.9,33.3 12.9,24.38
TL_AVDD1V4 on POWER: 14.3,48.2 14.3,44.7 17.7,41.3 17.7,36.1 17.52,36.1 17.52,35.3 23.47,35.3 23.47,36.05 22.72,36.8 19.8,36.8 19.6,37 19.6,44.4 15.8,48.2
TL_VBAT on POWER: 17.57,9.82 17.57,33.88 22.46,33.88 22.46,9.82
TL_VBUS on POWER: 7.6,9.8 7.6,24.37 10.48,24.37 10.48,24.4 12.9,24.4 12.9,33.3 19.67,33.3 19.67,31.71 20.7,31.71 20.7,30.28 17.5,30.28 17.5,29.7 17.51,29.7 17.51,22.43 17.52,22.43 17.52,9.99 17.57,9.99 17.57,9.8
TL_VDD3_DCDC on POWER: 0.2,0.2 0.2,60.5 24.7,60.5 24.7,0.2 ; 2 cut-outs

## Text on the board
Ref Des/Silkscreen Bottom: TDI/E4 | TDO/E5 | C1 | C2 | C3 | C4 | GND | SWS | C5 | C6 | A3/TX | A4/RX | VBUS | 3V3 | TCK | TMS | C1T213A3V1_1 | 2020_09_24 | NC
Ref Des/Silkscreen Top: B | A | C | D
DISPLAY_TOP: FIGURE | SIZE | 0.3 | 0.9 | 1.0 | 1.7 | 2.1x0.7 | DRILL CHART: TOP to BOTTOM | ALL UNITS ARE IN MILLIMETERS | PLATED | NON-PLATED | QTY | 185 | 24 | 4 | 2
